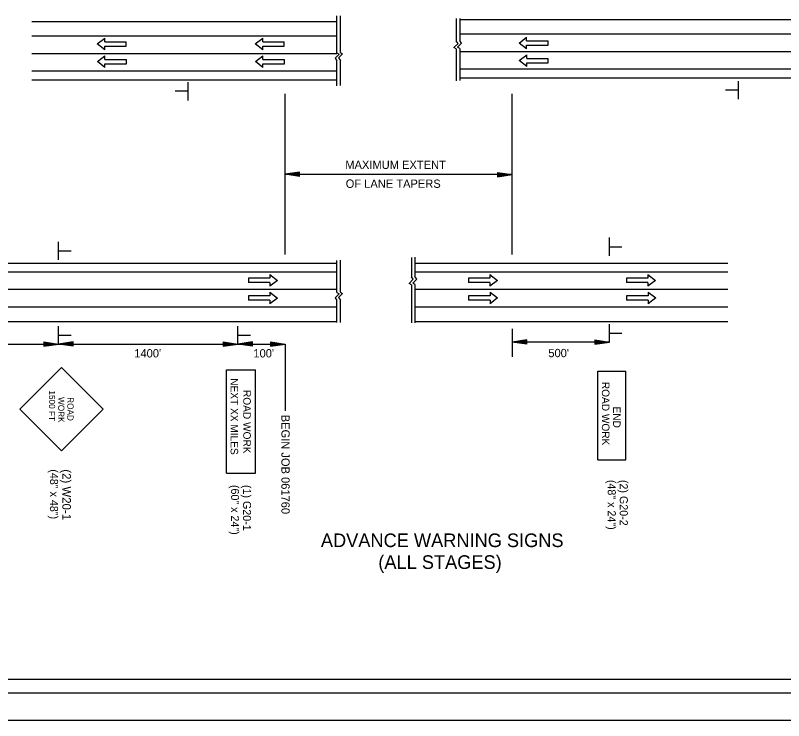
# Model space of a CAD drawing. Extents: x -500 to 213, y 382723 to 382830.
# Drawn here: x -442.4 to -386.5, y 382723.1 to 382774.3 of the extents above; entities that cross this region are included whole.
import ezdxf

# ---------------------------------------------------------------- set-up
doc = ezdxf.new("R2010")
doc.units = 0
for name, color, linetype in [('Default', 7, 'Continuous'), ('R_Border', 7, 'Continuous'), ('R_Detour', 7, 'Continuous'), ('R_Draft', 7, 'Continuous'), ('R_MOT', 7, 'Continuous'), ('R_No Plot', 7, 'Continuous')]:
    doc.layers.add(name, color=color, linetype=linetype)

msp = doc.modelspace()

# ---------------------------------------------------------------- linework, layer by layer
at = {"layer": 'Default'}
for p, q in [((-441.171, 382773.913), (-419.007, 382773.913)), ((-419.007, 382771.637), (-419.007, 382774.303)), ((-419.007, 382771.637), (-419.007, 382774.303)), ((-418.752, 382771.655), (-418.752, 382774.322)), ((-418.752, 382771.655), (-418.752, 382774.322)), ((-410.335, 382774.108), (-410.335, 382772.492)), ((-410.08, 382774.127), (-410.08, 382772.51)), ((-351.369, 382774.032), (-410.08, 382774.032)), ((-441.171, 382772.853), (-419.007, 382772.853)), ((-436.416, 382772.271), (-435.866, 382772.695)), ((-435.866, 382772.43), (-435.866, 382772.695)), ((-424.935, 382772.271), (-424.385, 382772.695)), ((-424.385, 382772.43), (-424.385, 382772.695)), ((-351.369, 382772.973), (-410.08, 382772.973)), ((-405.77, 382772.34), (-405.22, 382772.764)), ((-405.22, 382772.499), (-405.22, 382772.764)), ((-435.866, 382771.848), (-436.416, 382772.271)), ((-435.866, 382772.43), (-434.307, 382772.43)), ((-435.866, 382772.112), (-434.307, 382772.112)), ((-435.866, 382771.848), (-435.866, 382772.112)), ((-434.307, 382772.112), (-434.307, 382772.43)), ((-424.385, 382771.848), (-424.935, 382772.271)), ((-424.385, 382772.43), (-422.827, 382772.43)), ((-424.385, 382772.112), (-422.827, 382772.112)), ((-424.385, 382771.848), (-424.385, 382772.112)), ((-422.827, 382772.112), (-422.827, 382772.43)), ((-405.22, 382771.916), (-405.77, 382772.34)), ((-405.22, 382772.499), (-403.661, 382772.499)), ((-405.22, 382772.181), (-403.661, 382772.181)), ((-405.22, 382771.916), (-405.22, 382772.181)), ((-403.661, 382772.181), (-403.661, 382772.499)), ((-441.171, 382771.582), (-419.007, 382771.582)), ((-410.335, 382771.911), (-410.335, 382769.593)), ((-410.08, 382771.929), (-410.08, 382769.611)), ((-351.369, 382771.702), (-410.08, 382771.702)), ((-436.407, 382770.989), (-435.858, 382771.413)), ((-435.858, 382770.565), (-436.407, 382770.989)), ((-435.858, 382771.148), (-435.858, 382771.413)), ((-435.858, 382771.148), (-434.299, 382771.148)), ((-434.299, 382770.83), (-434.299, 382771.148)), ((-424.927, 382770.989), (-424.377, 382771.413)), ((-424.377, 382770.565), (-424.927, 382770.989)), ((-424.377, 382771.148), (-424.377, 382771.413)), ((-424.377, 382771.148), (-422.819, 382771.148)), ((-422.819, 382770.83), (-422.819, 382771.148)), ((-419.007, 382769.228), (-419.007, 382771.056)), ((-419.007, 382769.228), (-419.007, 382771.056)), ((-418.752, 382769.246), (-418.752, 382771.074)), ((-418.752, 382769.246), (-418.752, 382771.074)), ((-405.761, 382771.058), (-405.211, 382771.481)), ((-405.211, 382770.634), (-405.761, 382771.058)), ((-405.211, 382771.217), (-405.211, 382771.481)), ((-405.211, 382771.217), (-403.653, 382771.217)), ((-403.653, 382770.899), (-403.653, 382771.217)), ((-435.858, 382770.83), (-434.299, 382770.83)), ((-435.858, 382770.565), (-435.858, 382770.83)), ((-424.377, 382770.83), (-422.819, 382770.83)), ((-424.377, 382770.565), (-424.377, 382770.83)), ((-351.369, 382770.43), (-410.08, 382770.43)), ((-405.211, 382770.899), (-403.653, 382770.899)), ((-405.211, 382770.634), (-405.211, 382770.899)), ((-441.171, 382770.311), (-419.007, 382770.311)), ((-441.171, 382769.675), (-419.007, 382769.675)), ((-351.369, 382769.795), (-410.08, 382769.795)), ((-422.773, 382756.971), (-422.773, 382768.649)), ((-406.269, 382756.971), (-406.269, 382768.649)), ((-422.773, 382762.81), (-406.269, 382762.81)), ((-419.007, 382754.229), (-419.007, 382756.547)), ((-418.752, 382754.247), (-418.752, 382756.565)), ((-413.587, 382756.766), (-413.587, 382755.361)), ((-413.332, 382756.784), (-413.332, 382755.379)), ((-477.718, 382756.363), (-419.007, 382756.363)), ((-390.607, 382756.337), (-413.332, 382756.337)), ((-477.718, 382755.728), (-419.007, 382755.728)), ((-423.875, 382755.524), (-423.875, 382755.259)), ((-423.875, 382755.524), (-423.325, 382755.1)), ((-390.607, 382755.701), (-413.332, 382755.701)), ((-407.885, 382755.528), (-407.885, 382755.263)), ((-407.885, 382755.528), (-407.335, 382755.104)), ((-396.404, 382755.528), (-396.404, 382755.263)), ((-396.404, 382755.528), (-395.854, 382755.104)), ((-423.875, 382755.259), (-425.433, 382755.259)), ((-425.433, 382755.259), (-425.433, 382754.941)), ((-423.875, 382754.941), (-425.433, 382754.941)), ((-423.325, 382755.1), (-423.875, 382754.677)), ((-423.875, 382754.941), (-423.875, 382754.677)), ((-413.332, 382754.798), (-413.332, 382752.023)), ((-407.885, 382755.263), (-409.443, 382755.263)), ((-409.443, 382755.263), (-409.443, 382754.945)), ((-407.885, 382754.945), (-409.443, 382754.945)), ((-407.335, 382755.104), (-407.885, 382754.68)), ((-407.885, 382754.945), (-407.885, 382754.68)), ((-396.404, 382755.263), (-397.963, 382755.263)), ((-397.963, 382755.263), (-397.963, 382754.945)), ((-396.404, 382754.945), (-397.963, 382754.945)), ((-395.854, 382755.104), (-396.404, 382754.68)), ((-396.404, 382754.945), (-396.404, 382754.68)), ((-477.718, 382754.456), (-419.007, 382754.456)), ((-423.866, 382754.242), (-423.866, 382753.977)), ((-423.866, 382754.242), (-423.316, 382753.818)), ((-413.587, 382754.78), (-413.587, 382752.023)), ((-390.607, 382754.43), (-413.332, 382754.43)), ((-407.876, 382754.245), (-407.876, 382753.981)), ((-407.876, 382754.245), (-407.326, 382753.822)), ((-396.396, 382754.245), (-396.396, 382753.981)), ((-396.396, 382754.245), (-395.846, 382753.822)), ((-423.866, 382753.977), (-425.425, 382753.977)), ((-425.425, 382753.977), (-425.425, 382753.659)), ((-423.316, 382753.818), (-423.866, 382753.394)), ((-407.876, 382753.981), (-409.435, 382753.981)), ((-409.435, 382753.981), (-409.435, 382753.663)), ((-407.326, 382753.822), (-407.876, 382753.398)), ((-396.396, 382753.981), (-397.954, 382753.981)), ((-397.954, 382753.981), (-397.954, 382753.663)), ((-395.846, 382753.822), (-396.396, 382753.398)), ((-477.718, 382753.185), (-419.007, 382753.185)), ((-423.866, 382753.659), (-425.425, 382753.659)), ((-423.866, 382753.659), (-423.866, 382753.394)), ((-419.007, 382752.031), (-419.007, 382753.648)), ((-418.752, 382752.05), (-418.752, 382753.666)), ((-390.607, 382753.158), (-413.332, 382753.158)), ((-407.876, 382753.663), (-409.435, 382753.663)), ((-407.876, 382753.663), (-407.876, 382753.398)), ((-396.396, 382753.663), (-397.954, 382753.663)), ((-396.396, 382753.663), (-396.396, 382753.398)), ((-477.718, 382752.126), (-419.007, 382752.126)), ((-390.607, 382752.099), (-413.332, 382752.099)), ((-406.269, 382751.578), (-406.269, 382749.544)), ((-448.329, 382750.478), (-439.233, 382750.478)), ((-439.233, 382750.478), (-426.203, 382750.478)), ((-426.203, 382750.478), (-422.773, 382750.478)), ((-422.773, 382750.478), (-422.773, 382745.622)), ((-399.207, 382750.621), (-406.269, 382750.621))]:
    msp.add_line(p, q, dxfattribs=at)
for points in [[(-410.335, 382771.911), (-410.498, 382772.008), (-410.206, 382772.309), (-410.335, 382772.492)], [(-410.08, 382771.929), (-410.243, 382772.026), (-409.951, 382772.327), (-410.08, 382772.51)], [(-419.007, 382771.637), (-418.843, 382771.54), (-419.135, 382771.239), (-419.007, 382771.056)], [(-419.007, 382771.637), (-418.843, 382771.54), (-419.135, 382771.239), (-419.007, 382771.056)], [(-418.752, 382771.655), (-418.588, 382771.558), (-418.88, 382771.257), (-418.752, 382771.074)], [(-418.752, 382771.655), (-418.588, 382771.558), (-418.88, 382771.257), (-418.752, 382771.074)], [(-413.587, 382754.78), (-413.751, 382754.878), (-413.459, 382755.178), (-413.587, 382755.361)], [(-413.332, 382754.798), (-413.495, 382754.896), (-413.204, 382755.197), (-413.332, 382755.379)], [(-418.752, 382754.247), (-418.588, 382754.15), (-418.88, 382753.849), (-418.752, 382753.666)], [(-419.007, 382754.229), (-418.843, 382754.132), (-419.135, 382753.831), (-419.007, 382753.648)]]:
    msp.add_lwpolyline(points, dxfattribs=at)
at = {"layer": 'R_Border'}
msp.add_line((-335.908, 382725.12), (-493.998, 382725.12), dxfattribs=at)
at = {"layer": 'R_Detour'}
for p, q in [((-427.015, 382741.095), (-427.015, 382748.599)), ((-427.015, 382748.599), (-424.929, 382748.599)), ((-424.929, 382741.095), (-424.929, 382748.599)), ((-427.015, 382741.095), (-424.929, 382741.095))]:
    msp.add_line(p, q, dxfattribs=at)
at = {"layer": 'R_Draft'}
for p, q in [((-421.714, 382762.969), (-422.773, 382762.81)), ((-421.714, 382762.651), (-422.773, 382762.81)), ((-421.714, 382762.942), (-422.596, 382762.81)), ((-421.714, 382762.677), (-422.596, 382762.81)), ((-421.714, 382762.915), (-422.414, 382762.81)), ((-421.714, 382762.704), (-422.414, 382762.81)), ((-421.714, 382762.889), (-422.238, 382762.81)), ((-421.714, 382762.731), (-422.238, 382762.81)), ((-421.714, 382762.862), (-422.058, 382762.81)), ((-421.714, 382762.758), (-422.058, 382762.81)), ((-421.714, 382762.835), (-421.881, 382762.81)), ((-421.714, 382762.785), (-421.881, 382762.81)), ((-421.714, 382762.651), (-421.714, 382762.969)), ((-407.329, 382762.942), (-406.269, 382762.783)), ((-407.329, 382762.942), (-407.329, 382762.624)), ((-407.329, 382762.916), (-406.446, 382762.783)), ((-407.329, 382762.889), (-406.629, 382762.783)), ((-407.329, 382762.862), (-406.805, 382762.783)), ((-407.329, 382762.835), (-406.985, 382762.783)), ((-407.329, 382762.808), (-407.162, 382762.783)), ((-407.329, 382762.624), (-406.269, 382762.783)), ((-407.329, 382762.731), (-406.985, 382762.783)), ((-407.329, 382762.678), (-406.629, 382762.783)), ((-407.329, 382762.651), (-406.446, 382762.783)), ((-407.329, 382762.704), (-406.805, 382762.783)), ((-407.329, 382762.758), (-407.162, 382762.783)), ((-440.292, 382750.636), (-439.233, 382750.478)), ((-440.292, 382750.636), (-440.292, 382750.319)), ((-440.292, 382750.61), (-439.409, 382750.478)), ((-440.292, 382750.583), (-439.592, 382750.478)), ((-440.292, 382750.556), (-439.768, 382750.478)), ((-440.292, 382750.529), (-439.948, 382750.478)), ((-440.292, 382750.502), (-440.125, 382750.478)), ((-440.292, 382750.319), (-439.233, 382750.478)), ((-440.292, 382750.426), (-439.948, 382750.478)), ((-440.292, 382750.372), (-439.592, 382750.478)), ((-440.292, 382750.345), (-439.409, 382750.478)), ((-440.292, 382750.399), (-439.768, 382750.478)), ((-440.292, 382750.453), (-440.125, 382750.478)), ((-438.173, 382750.636), (-439.233, 382750.478)), ((-438.173, 382750.319), (-439.233, 382750.478)), ((-438.173, 382750.61), (-439.056, 382750.478)), ((-438.173, 382750.345), (-439.056, 382750.478)), ((-438.173, 382750.583), (-438.873, 382750.478)), ((-438.173, 382750.372), (-438.873, 382750.478)), ((-438.173, 382750.556), (-438.697, 382750.478)), ((-438.173, 382750.399), (-438.697, 382750.478)), ((-438.173, 382750.529), (-438.517, 382750.478)), ((-438.173, 382750.426), (-438.517, 382750.478)), ((-438.173, 382750.502), (-438.341, 382750.478)), ((-438.173, 382750.453), (-438.341, 382750.478)), ((-438.173, 382750.319), (-438.173, 382750.636)), ((-427.263, 382750.636), (-426.203, 382750.478)), ((-427.263, 382750.636), (-427.263, 382750.319)), ((-427.263, 382750.61), (-426.38, 382750.478)), ((-427.263, 382750.583), (-426.563, 382750.478)), ((-427.263, 382750.556), (-426.739, 382750.478)), ((-427.263, 382750.529), (-426.919, 382750.478)), ((-427.263, 382750.502), (-427.095, 382750.478)), ((-427.263, 382750.319), (-426.203, 382750.478)), ((-427.263, 382750.426), (-426.919, 382750.478)), ((-427.263, 382750.372), (-426.563, 382750.478)), ((-427.263, 382750.345), (-426.38, 382750.478)), ((-427.263, 382750.399), (-426.739, 382750.478)), ((-427.263, 382750.453), (-427.095, 382750.478)), ((-425.144, 382750.636), (-426.203, 382750.478)), ((-425.144, 382750.319), (-426.203, 382750.478)), ((-425.144, 382750.61), (-426.027, 382750.478)), ((-425.144, 382750.345), (-426.027, 382750.478)), ((-425.144, 382750.583), (-425.844, 382750.478)), ((-425.144, 382750.372), (-425.844, 382750.478)), ((-425.144, 382750.556), (-425.668, 382750.478)), ((-425.144, 382750.399), (-425.668, 382750.478)), ((-425.144, 382750.529), (-425.488, 382750.478)), ((-425.144, 382750.426), (-425.488, 382750.478)), ((-425.144, 382750.502), (-425.311, 382750.478)), ((-425.144, 382750.453), (-425.311, 382750.478)), ((-425.144, 382750.319), (-425.144, 382750.636)), ((-423.833, 382750.636), (-422.773, 382750.478)), ((-423.833, 382750.636), (-423.833, 382750.319)), ((-423.833, 382750.61), (-422.95, 382750.478)), ((-423.833, 382750.583), (-423.132, 382750.478)), ((-423.833, 382750.556), (-423.309, 382750.478)), ((-423.833, 382750.529), (-423.488, 382750.478)), ((-423.833, 382750.502), (-423.665, 382750.478)), ((-423.833, 382750.319), (-422.773, 382750.478)), ((-423.833, 382750.426), (-423.488, 382750.478)), ((-423.833, 382750.372), (-423.132, 382750.478)), ((-423.833, 382750.345), (-422.95, 382750.478)), ((-423.833, 382750.399), (-423.309, 382750.478)), ((-423.833, 382750.453), (-423.665, 382750.478)), ((-405.21, 382750.78), (-406.269, 382750.621)), ((-405.21, 382750.463), (-406.269, 382750.621)), ((-405.21, 382750.754), (-406.092, 382750.621)), ((-405.21, 382750.489), (-406.092, 382750.621)), ((-405.21, 382750.727), (-405.91, 382750.621)), ((-405.21, 382750.516), (-405.91, 382750.621)), ((-405.21, 382750.7), (-405.734, 382750.621)), ((-405.21, 382750.542), (-405.734, 382750.621)), ((-405.21, 382750.673), (-405.554, 382750.621)), ((-405.21, 382750.57), (-405.554, 382750.621)), ((-405.21, 382750.646), (-405.377, 382750.621)), ((-405.21, 382750.597), (-405.377, 382750.621)), ((-405.21, 382750.463), (-405.21, 382750.78)), ((-400.266, 382750.78), (-399.207, 382750.621)), ((-400.266, 382750.78), (-400.266, 382750.463)), ((-400.266, 382750.754), (-399.384, 382750.621)), ((-400.266, 382750.727), (-399.566, 382750.621)), ((-400.266, 382750.7), (-399.742, 382750.621)), ((-400.266, 382750.673), (-399.922, 382750.621)), ((-400.266, 382750.646), (-400.099, 382750.621)), ((-400.266, 382750.463), (-399.207, 382750.621)), ((-400.266, 382750.57), (-399.922, 382750.621)), ((-400.266, 382750.516), (-399.566, 382750.621)), ((-400.266, 382750.489), (-399.384, 382750.621)), ((-400.266, 382750.542), (-399.742, 382750.621)), ((-400.266, 382750.597), (-400.099, 382750.621))]:
    msp.add_line(p, q, dxfattribs=at)
at = {"layer": 'R_MOT'}
for p, q in [((-429.838, 382769.484), (-429.838, 382768.175)), ((-389.854, 382769.562), (-389.854, 382768.253)), ((-429.857, 382768.832), (-430.75, 382768.832)), ((-389.873, 382768.911), (-390.766, 382768.91)), ((-399.207, 382756.895), (-399.207, 382758.204)), ((-439.233, 382756.596), (-439.233, 382757.905)), ((-439.213, 382757.247), (-438.32, 382757.248)), ((-399.188, 382757.546), (-398.294, 382757.546)), ((-439.233, 382750.478), (-439.233, 382751.786)), ((-426.203, 382750.478), (-426.203, 382751.786)), ((-399.207, 382750.621), (-399.207, 382751.93)), ((-439.213, 382751.129), (-438.32, 382751.129)), ((-426.184, 382751.129), (-425.291, 382751.129)), ((-399.188, 382751.273), (-398.294, 382751.273)), ((-442.044, 382745.743), (-439.016, 382748.774)), ((-435.985, 382745.743), (-439.016, 382748.774)), ((-400.037, 382742.074), (-400.037, 382748.511)), ((-400.037, 382748.511), (-398.015, 382748.511)), ((-398.015, 382742.074), (-398.015, 382748.511)), ((-439.016, 382742.713), (-442.044, 382745.743)), ((-439.016, 382742.713), (-435.985, 382745.743)), ((-400.037, 382742.074), (-398.015, 382742.074))]:
    msp.add_line(p, q, dxfattribs=at)
at = {"layer": 'R_No Plot'}
for points in [[(-500.202, 382829.798), (-333.532, 382829.798), (-333.532, 382723.129), (-500.202, 382723.129)], [(-492.998, 382826.85), (-368.228, 382826.85), (-368.228, 382821.91), (-359.458, 382821.91), (-347.408, 382821.91), (-347.408, 382810.744), (-336.908, 382810.744), (-336.908, 382726.12), (-492.998, 382726.12)], [(-492.998, 382775.485), (-336.908, 382775.485), (-336.908, 382726.12), (-492.998, 382726.12)]]:
    msp.add_lwpolyline(points, close=True, dxfattribs=at)

# ---------------------------------------------------------------- texts
at = {"layer": 'Default'}
for s, height, p in [('MAXIMUM EXTENT', 0.60315, (-418.395, 382763.195)), ('OF LANE TAPERS', 0.60315, (-418.365, 382761.822)), ("1400'", 0.6031, (-433.725, 382749.505)), ("100'", 0.6031, (-425.072, 382749.505)), ("500'", 0.6031, (-403.644, 382749.522)), ('ADVANCE WARNING SIGNS', 0.98877, (-420.169, 382735.73)), ('(ALL STAGES)', 0.98877, (-415.995, 382734.148))]:
    msp.add_text(s, height=height, dxfattribs=at).set_placement(p)
msp.add_text('BEGIN JOB 061760', height=0.60315, rotation=270, dxfattribs=at).set_placement((-423.038, 382745.344))
at = {"layer": 'R_MOT'}
for s, height, rotation, p in [('NEXT XX MILES', 0.54947, 270, (-426.73, 382747.993)), ('ROAD WORK', 0.5495, 270, (-399.752, 382747.732)), ('1500 FT', 0.4465, 270.0006, (-439.923, 382747.109)), ('ROAD WORK', 0.5495, 270, (-425.809, 382747.141)), ('WORK', 0.4464, 270, (-439.254, 382746.628)), ('ROAD', 0.4465, 270.0004, (-438.584, 382746.619)), ('END', 0.5495, 270, (-398.94, 382745.938)), ('(48" x 48")', 0.5814, 270, (-439.844, 382741.379)), ('(2) W20-1', 0.6202, 270, (-438.951, 382741.379)), ('(48" x 24")', 0.5814, 270, (-399.325, 382740.613)), ('(2) G20-2', 0.5815, 270, (-398.453, 382740.613)), ('(60" x 24")', 0.5814, 270, (-426.696, 382740.247)), ('(1) G20-1', 0.5815, 270, (-425.824, 382740.247))]:
    msp.add_text(s, height=height, rotation=rotation, dxfattribs=at).set_placement(p)

doc.saveas('drawing.dxf')
